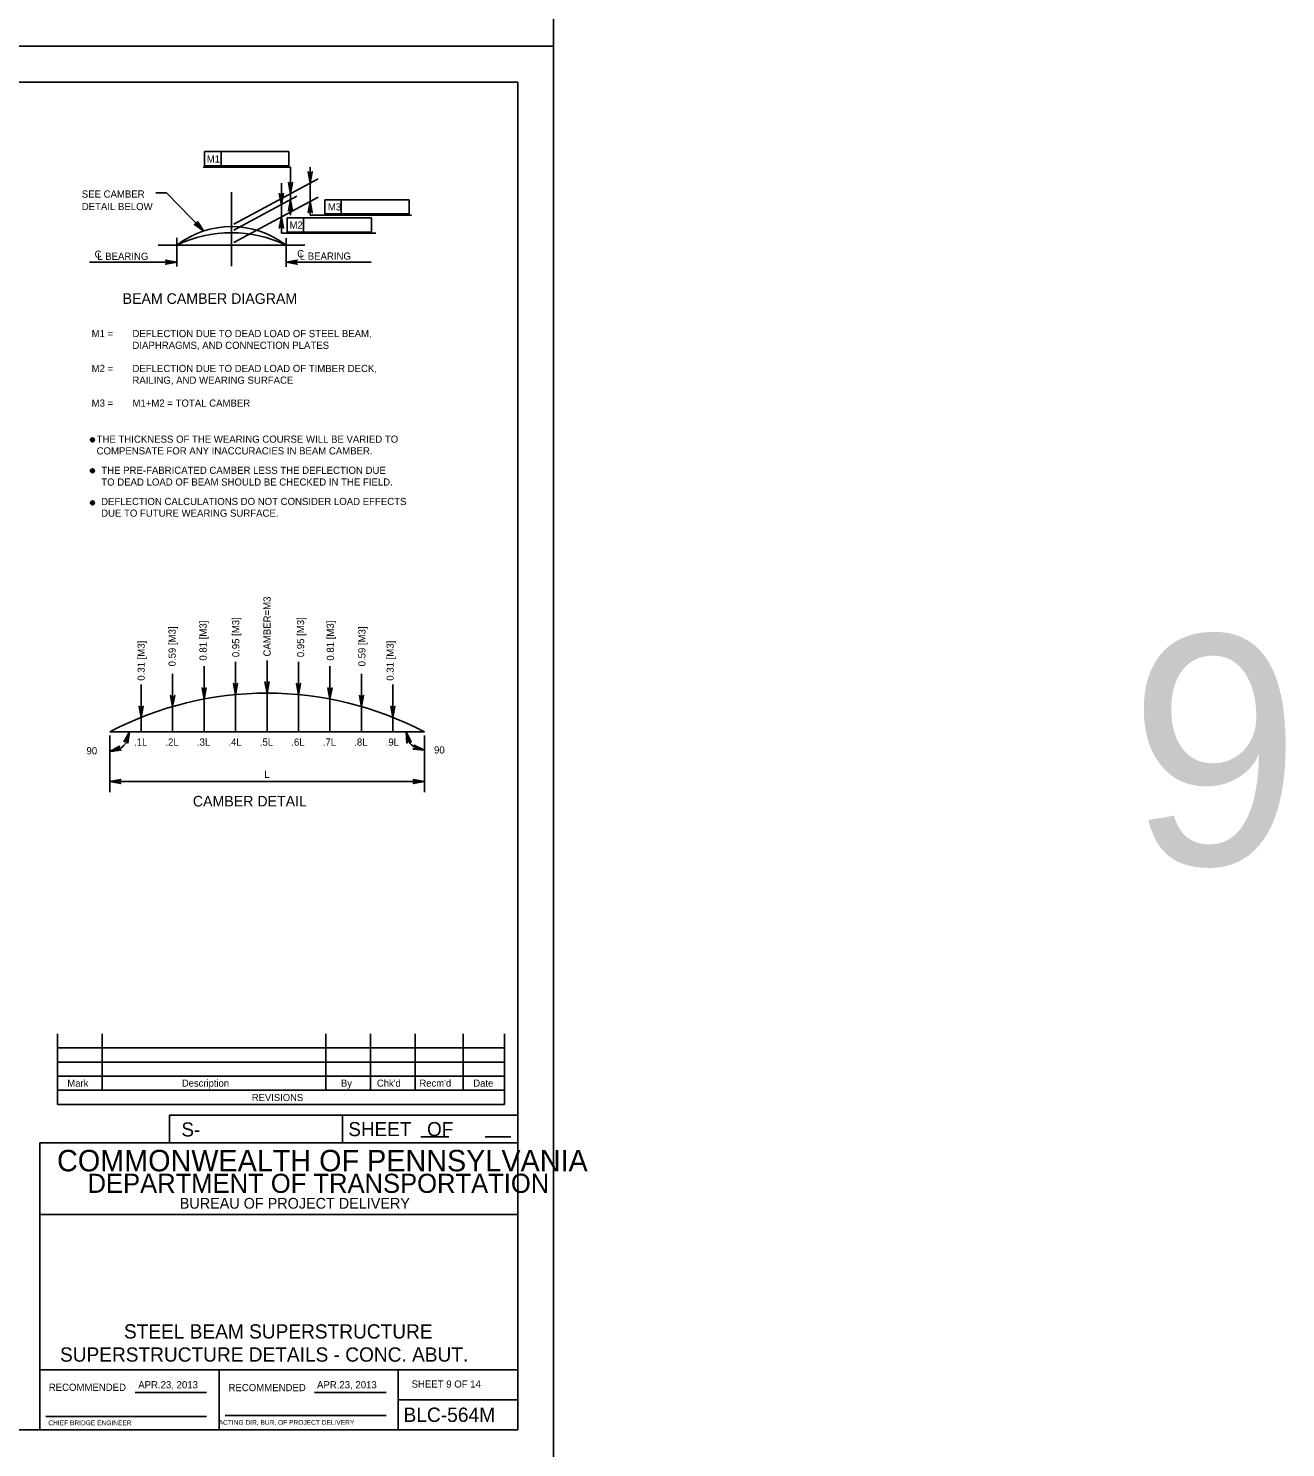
# Model space of a CAD drawing. Extents: x 638175 to 640495, y 294277 to 298435.
# Drawn here: x 639898 to 640424, y 297255 to 297849 of the extents above; entities that cross this region are included whole.
import ezdxf

# ---------------------------------------------------------------- set-up
doc = ezdxf.new("R2010")
doc.units = 0
for name, color, linetype in [('1', 7, 'Continuous'), ('2', 7, 'Continuous'), ('3', 7, 'Continuous'), ('4', 7, 'Continuous'), ('5', 7, 'Continuous'), ('53', 7, 'Continuous'), ('6', 7, 'Continuous'), ('PLT-BNDY', 7, 'Continuous')]:
    doc.layers.add(name, color=color, linetype=linetype)

msp = doc.modelspace()

# ---------------------------------------------------------------- linework, layer by layer
at = {"layer": '2'}
for p, q in [((639316.46, 297826.46), (640102.46, 297826.46)), ((640102.46, 297826.46), (640102.46, 297262.46)), ((639909.92, 297428.15), (639909.92, 297398.62)), ((639928.62, 297428.15), (639928.62, 297404.53)), ((640022.13, 297428.15), (640022.13, 297404.53)), ((640040.83, 297428.15), (640040.83, 297404.53)), ((640059.53, 297428.15), (640059.53, 297404.53)), ((640079.59, 297428.15), (640079.59, 297404.53)), ((640096.94, 297428.15), (640096.94, 297398.62)), ((640096.94, 297422.24), (639909.92, 297422.24)), ((640096.94, 297416.34), (639909.92, 297416.34)), ((640096.94, 297410.43), (639909.92, 297410.43)), ((640096.94, 297404.53), (639909.92, 297404.53)), ((640096.94, 297398.62), (639909.92, 297398.62)), ((640102.46, 297394.11), (639956.78, 297394.11)), ((639956.78, 297394.11), (639956.78, 297382.46)), ((640029.09, 297394.11), (640029.09, 297382.46)), ((640102.46, 297382.46), (639902.46, 297382.46)), ((639902.46, 297382.46), (639902.46, 297262.46)), ((640061.95, 297385), (640073.6, 297385)), ((640088.83, 297385), (640099.56, 297385)), ((640102.46, 297352.46), (639902.46, 297352.46)), ((640102.46, 297287.46), (639902.46, 297287.46)), ((639977.46, 297262.46), (639977.46, 297287.46)), ((640052.46, 297287.46), (640052.46, 297262.46)), ((639942.42, 297277.96), (639972.19, 297277.96)), ((640017.42, 297277.96), (640047.33, 297277.96)), ((640052.46, 297274.96), (640102.46, 297274.96)), ((639904.96, 297267.96), (639972.19, 297267.96)), ((639980.08, 297268.33), (640047.33, 297268.33)), ((640102.46, 297262.46), (639316.46, 297262.46))]:
    msp.add_line(p, q, dxfattribs=at)
at = {"layer": '3'}
for p, q in [((639971.42, 297797.39), (640006.72, 297797.39)), ((639971.42, 297791.48), (639971.42, 297797.39)), ((639978.31, 297791.48), (639978.31, 297797.39)), ((640006.72, 297797.39), (640006.72, 297791.48)), ((640007.35, 297790.9), (639970.86, 297790.9)), ((640006.72, 297791.48), (639971.42, 297791.48)), ((640007.35, 297790.9), (640007.35, 297770.78)), ((640015.62, 297780.3), (640015.62, 297790.9)), ((639983.73, 297767.05), (640018.91, 297786.05)), ((640003.55, 297763.19), (640003.55, 297784.12)), ((639955.5, 297780.06), (639951, 297780.06)), ((639971.05, 297764.14), (639955.5, 297780.06)), ((639982.67, 297749.49), (639982.67, 297780.43)), ((639983.73, 297764.46), (640010.06, 297778.69)), ((639983.73, 297759.29), (640018.91, 297778.3)), ((640015.62, 297780.3), (640015.62, 297770.78)), ((640021.68, 297777.23), (640056.98, 297777.23)), ((640021.68, 297771.32), (640021.68, 297777.23)), ((640028.57, 297771.32), (640028.57, 297777.23)), ((640056.98, 297777.23), (640056.98, 297771.32)), ((640005.95, 297769.61), (640041.25, 297769.61)), ((640005.95, 297763.71), (640005.95, 297769.61)), ((640012.84, 297763.71), (640012.84, 297769.61)), ((640057.99, 297770.78), (640015.62, 297770.78)), ((640056.98, 297771.32), (640021.68, 297771.32)), ((640041.25, 297769.61), (640041.25, 297763.71)), ((639959.79, 297761.27), (639959.79, 297749.35)), ((640043.06, 297763.19), (640003.55, 297763.19)), ((640005.55, 297761.14), (640005.55, 297749.22)), ((640041.25, 297763.71), (640005.95, 297763.71)), ((639959.79, 297751.09), (639923.31, 297751.09)), ((640005.55, 297751.09), (640041.11, 297751.09)), ((639984.39, 297570.12), (639984.39, 297583.84)), ((639997.55, 297570.74), (639997.55, 297584.45)), ((640010.72, 297570.12), (640010.72, 297583.84)), ((639958.05, 297565.13), (639958.05, 297578.84)), ((639971.22, 297568.27), (639971.22, 297581.98)), ((640023.89, 297568.27), (640023.89, 297581.98)), ((640037.05, 297565.13), (640037.05, 297578.84)), ((639944.89, 297560.6), (639944.89, 297574.31)), ((640050.22, 297560.6), (640050.22, 297574.31)), ((639931.72, 297552.97), (639931.72, 297529.28)), ((640063.39, 297552.97), (640063.39, 297529.28)), ((639931.72, 297533.78), (640063.39, 297533.78))]:
    msp.add_line(p, q, dxfattribs=at)
for points in [[(640007.35, 297779.8), (640006.48, 297784.46), (640006.73, 297784.11), (640007.04, 297783.92), (640007.35, 297783.87), (640007.66, 297783.92), (640007.98, 297784.11), (640008.22, 297784.46), (640007.35, 297779.8), (640007.98, 297784.11), (640007.66, 297783.92), (640007.35, 297779.8), (640007.35, 297783.87), (640007.04, 297783.92), (640007.35, 297779.8), (640006.73, 297784.11)], [(640015.62, 297784.27), (640014.75, 297788.93), (640014.99, 297788.57), (640015.31, 297788.39), (640015.62, 297788.33), (640015.93, 297788.39), (640016.24, 297788.57), (640016.49, 297788.93), (640015.62, 297784.27), (640016.24, 297788.57), (640015.93, 297788.39), (640015.62, 297784.27), (640015.62, 297788.33), (640015.31, 297788.39), (640015.62, 297784.27), (640014.99, 297788.57)], [(640003.55, 297775.17), (640002.68, 297779.83), (640002.93, 297779.47), (640003.24, 297779.29), (640003.55, 297779.23), (640003.86, 297779.29), (640004.18, 297779.47), (640004.42, 297779.83), (640003.55, 297775.17), (640004.18, 297779.47), (640003.86, 297779.29), (640003.55, 297775.17), (640003.55, 297779.23), (640003.24, 297779.29), (640003.55, 297775.17), (640002.93, 297779.47)], [(640007.35, 297777.22), (640008.22, 297772.56), (640007.98, 297772.92), (640007.66, 297773.1), (640007.35, 297773.16), (640007.04, 297773.1), (640006.73, 297772.92), (640006.48, 297772.56), (640007.35, 297777.22), (640006.73, 297772.92), (640007.04, 297773.1), (640007.35, 297777.22), (640007.35, 297773.16), (640007.66, 297773.1), (640007.35, 297777.22), (640007.98, 297772.92)], [(640015.62, 297776.52), (640016.49, 297771.86), (640016.24, 297772.22), (640015.93, 297772.4), (640015.62, 297772.46), (640015.31, 297772.4), (640014.99, 297772.22), (640014.75, 297771.86), (640015.62, 297776.52), (640014.99, 297772.22), (640015.31, 297772.4), (640015.62, 297776.52), (640015.62, 297772.46), (640015.93, 297772.4), (640015.62, 297776.52), (640016.24, 297772.22)], [(639971.05, 297764.14), (639967.17, 297766.87), (639967.6, 297766.78), (639967.95, 297766.87), (639968.21, 297767.05), (639968.4, 297767.31), (639968.5, 297767.66), (639968.42, 297768.09), (639971.05, 297764.14), (639968.5, 297767.66), (639968.4, 297767.31), (639971.05, 297764.14), (639968.21, 297767.05), (639967.95, 297766.87), (639971.05, 297764.14), (639967.6, 297766.78)], [(640003.55, 297770), (640004.42, 297765.34), (640004.18, 297765.7), (640003.86, 297765.88), (640003.55, 297765.94), (640003.24, 297765.88), (640002.93, 297765.7), (640002.68, 297765.34), (640003.55, 297770), (640002.93, 297765.7), (640003.24, 297765.88), (640003.55, 297770), (640003.55, 297765.94), (640003.86, 297765.88), (640003.55, 297770), (640004.18, 297765.7)], [(639959.79, 297751.09), (639955.12, 297750.22), (639955.48, 297750.47), (639955.67, 297750.78), (639955.72, 297751.09), (639955.67, 297751.41), (639955.48, 297751.72), (639955.12, 297751.97), (639959.79, 297751.09), (639955.48, 297751.72), (639955.67, 297751.41), (639959.79, 297751.09), (639955.72, 297751.09), (639955.67, 297750.78), (639959.79, 297751.09), (639955.48, 297750.47)], [(640005.55, 297751.09), (640010.21, 297751.97), (640009.85, 297751.72), (640009.67, 297751.41), (640009.61, 297751.09), (640009.67, 297750.78), (640009.85, 297750.47), (640010.21, 297750.22), (640005.55, 297751.09), (640009.85, 297750.47), (640009.67, 297750.78), (640005.55, 297751.09), (640009.61, 297751.09), (640009.67, 297751.41), (640005.55, 297751.09), (640009.85, 297751.72)], [(639971.22, 297568.27), (639970.35, 297572.93), (639970.59, 297572.57), (639970.91, 297572.39), (639971.22, 297572.33), (639971.53, 297572.39), (639971.84, 297572.57), (639972.09, 297572.93), (639971.22, 297568.27), (639971.84, 297572.57), (639971.53, 297572.39), (639971.22, 297568.27), (639971.22, 297572.33), (639970.91, 297572.39), (639971.22, 297568.27), (639970.59, 297572.57)], [(639984.39, 297570.12), (639983.51, 297574.78), (639983.76, 297574.43), (639984.07, 297574.24), (639984.39, 297574.19), (639984.7, 297574.24), (639985.01, 297574.43), (639985.26, 297574.78), (639984.39, 297570.12), (639985.01, 297574.43), (639984.7, 297574.24), (639984.39, 297570.12), (639984.39, 297574.19), (639984.07, 297574.24), (639984.39, 297570.12), (639983.76, 297574.43)], [(639997.55, 297570.74), (639996.68, 297575.4), (639996.93, 297575.04), (639997.24, 297574.85), (639997.55, 297574.8), (639997.86, 297574.85), (639998.18, 297575.04), (639998.42, 297575.4), (639997.55, 297570.74), (639998.18, 297575.04), (639997.86, 297574.85), (639997.55, 297570.74), (639997.55, 297574.8), (639997.24, 297574.85), (639997.55, 297570.74), (639996.93, 297575.04)], [(640010.72, 297570.12), (640009.85, 297574.78), (640010.09, 297574.43), (640010.41, 297574.24), (640010.72, 297574.19), (640011.03, 297574.24), (640011.34, 297574.43), (640011.59, 297574.78), (640010.72, 297570.12), (640011.34, 297574.43), (640011.03, 297574.24), (640010.72, 297570.12), (640010.72, 297574.19), (640010.41, 297574.24), (640010.72, 297570.12), (640010.09, 297574.43)], [(640023.89, 297568.27), (640023.01, 297572.93), (640023.26, 297572.57), (640023.57, 297572.39), (640023.89, 297572.33), (640024.2, 297572.39), (640024.51, 297572.57), (640024.76, 297572.93), (640023.89, 297568.27), (640024.51, 297572.57), (640024.2, 297572.39), (640023.89, 297568.27), (640023.89, 297572.33), (640023.57, 297572.39), (640023.89, 297568.27), (640023.26, 297572.57)], [(639944.89, 297560.6), (639944.01, 297565.26), (639944.26, 297564.9), (639944.57, 297564.72), (639944.89, 297564.66), (639945.2, 297564.72), (639945.51, 297564.9), (639945.76, 297565.26), (639944.89, 297560.6), (639945.51, 297564.9), (639945.2, 297564.72), (639944.89, 297560.6), (639944.89, 297564.66), (639944.57, 297564.72), (639944.89, 297560.6), (639944.26, 297564.9)], [(639958.05, 297565.13), (639957.18, 297569.79), (639957.43, 297569.43), (639957.74, 297569.24), (639958.05, 297569.19), (639958.36, 297569.24), (639958.68, 297569.43), (639958.92, 297569.79), (639958.05, 297565.13), (639958.68, 297569.43), (639958.36, 297569.24), (639958.05, 297565.13), (639958.05, 297569.19), (639957.74, 297569.24), (639958.05, 297565.13), (639957.43, 297569.43)], [(640037.05, 297565.13), (640036.18, 297569.79), (640036.43, 297569.43), (640036.74, 297569.24), (640037.05, 297569.19), (640037.36, 297569.24), (640037.68, 297569.43), (640037.92, 297569.79), (640037.05, 297565.13), (640037.68, 297569.43), (640037.36, 297569.24), (640037.05, 297565.13), (640037.05, 297569.19), (640036.74, 297569.24), (640037.05, 297565.13), (640036.43, 297569.43)], [(640050.22, 297560.6), (640049.35, 297565.26), (640049.59, 297564.9), (640049.91, 297564.72), (640050.22, 297564.66), (640050.53, 297564.72), (640050.84, 297564.9), (640051.09, 297565.26), (640050.22, 297560.6), (640050.84, 297564.9), (640050.53, 297564.72), (640050.22, 297560.6), (640050.22, 297564.66), (640049.91, 297564.72), (640050.22, 297560.6), (640049.59, 297564.9)], [(639940.05, 297554.52), (639939.33, 297549.83), (639939.21, 297550.25), (639938.98, 297550.53), (639938.7, 297550.69), (639938.39, 297550.74), (639938.03, 297550.67), (639937.68, 297550.41), (639940.05, 297554.52), (639938.03, 297550.67), (639938.39, 297550.74), (639940.05, 297554.52), (639938.7, 297550.69), (639938.98, 297550.53), (639940.05, 297554.52), (639939.21, 297550.25)], [(640055.73, 297554.53), (640057.8, 297550.26), (640057.46, 297550.54), (640057.11, 297550.64), (640056.8, 297550.61), (640056.51, 297550.48), (640056.25, 297550.22), (640056.11, 297549.81), (640055.73, 297554.53), (640056.25, 297550.22), (640056.51, 297550.48), (640055.73, 297554.53), (640056.8, 297550.61), (640057.11, 297550.64), (640055.73, 297554.53), (640057.46, 297550.54)], [(639931.73, 297546.24), (639935.89, 297548.51), (639935.62, 297548.16), (639935.55, 297547.81), (639935.59, 297547.5), (639935.74, 297547.22), (639936.01, 297546.98), (639936.43, 297546.85), (639931.73, 297546.24), (639936.01, 297546.98), (639935.74, 297547.22), (639931.73, 297546.24), (639935.59, 297547.5), (639935.55, 297547.81), (639931.73, 297546.24), (639935.62, 297548.16)], [(640063.38, 297546.88), (640058.66, 297547.3), (640059.07, 297547.45), (640059.33, 297547.7), (640059.47, 297547.98), (640059.5, 297548.3), (640059.41, 297548.65), (640059.13, 297548.98), (640063.38, 297546.88), (640059.41, 297548.65), (640059.5, 297548.3), (640063.38, 297546.88), (640059.47, 297547.98), (640059.33, 297547.7), (640063.38, 297546.88), (640059.07, 297547.45)], [(639931.72, 297533.78), (639936.38, 297534.65), (639936.02, 297534.4), (639935.84, 297534.09), (639935.78, 297533.78), (639935.84, 297533.46), (639936.02, 297533.15), (639936.38, 297532.9), (639931.72, 297533.78), (639936.02, 297533.15), (639935.84, 297533.46), (639931.72, 297533.78), (639935.78, 297533.78), (639935.84, 297534.09), (639931.72, 297533.78), (639936.02, 297534.4)], [(640063.39, 297533.78), (640058.72, 297532.9), (640059.08, 297533.15), (640059.27, 297533.46), (640059.32, 297533.78), (640059.27, 297534.09), (640059.08, 297534.4), (640058.72, 297534.65), (640063.39, 297533.78), (640059.08, 297534.4), (640059.27, 297534.09), (640063.39, 297533.78), (640059.32, 297533.78), (640059.27, 297533.46), (640063.39, 297533.78), (640059.08, 297533.15)]]:
    msp.add_lwpolyline(points, dxfattribs=at)
for points in [[(640016.11, 297787.22), (640015.13, 297787.22), (640015.62, 297784.27)], [(640007.84, 297782.76), (640006.86, 297782.76), (640007.35, 297779.8)], [(640004.04, 297778.12), (640003.06, 297778.12), (640003.55, 297775.17)], [(640006.86, 297774.27), (640007.84, 297774.27), (640007.35, 297777.22)], [(640015.13, 297773.57), (640016.11, 297773.57), (640015.62, 297776.52)], [(639968.45, 297767.89), (639967.37, 297766.84), (639971.05, 297764.14)], [(640003.06, 297767.05), (640004.04, 297767.05), (640003.55, 297770)], [(639956.83, 297750.6), (639956.83, 297751.59), (639959.79, 297751.09)], [(640008.5, 297750.6), (640008.5, 297751.59), (640005.55, 297751.09)], [(639971.72, 297571.27), (639970.72, 297571.27), (639971.22, 297568.27)], [(639984.89, 297573.12), (639983.89, 297573.12), (639984.39, 297570.12)], [(639998.05, 297573.74), (639997.05, 297573.74), (639997.55, 297570.74)], [(640011.22, 297573.12), (640010.22, 297573.12), (640010.72, 297570.12)], [(640024.39, 297571.27), (640023.39, 297571.27), (640023.89, 297568.27)], [(639958.55, 297568.13), (639957.55, 297568.13), (639958.05, 297565.13)], [(640037.55, 297568.13), (640036.55, 297568.13), (640037.05, 297565.13)], [(639945.39, 297563.6), (639944.39, 297563.6), (639944.89, 297560.6)], [(640050.72, 297563.6), (640049.72, 297563.6), (640050.22, 297560.6)], [(639934.72, 297534.28), (639934.72, 297533.28), (639931.72, 297533.78)], [(640060.39, 297534.28), (640060.39, 297533.28), (640063.39, 297533.78)]]:
    msp.add_lwpolyline(points, close=True, dxfattribs=at)
for centre, radius in [((639924.52, 297676.74), 0.833), ((639924.52, 297676.74), 0.417), ((639924.52, 297663.81), 0.833), ((639924.52, 297663.81), 0.417), ((639924.52, 297650.38), 0.833), ((639924.52, 297650.38), 0.417)]:
    msp.add_circle(centre, radius, dxfattribs=at)
for centre, radius, start, end in [((639931.72, 297554.54), 8.24, 269.99961, 359.99852), ((640063.38, 297554.54), 7.62, 180.0016, 270.00489)]:
    msp.add_arc(centre, radius, start, end, dxfattribs=at)
at = {"layer": '5'}
for p, q in [((639997.55, 297570.74), (639997.55, 297554.54)), ((639958.05, 297565.13), (639958.05, 297554.54)), ((639971.22, 297568.27), (639971.22, 297554.54)), ((639984.39, 297570.12), (639984.39, 297554.54)), ((640010.72, 297570.12), (640010.72, 297554.54)), ((640023.89, 297568.27), (640023.89, 297554.54)), ((640037.05, 297565.13), (640037.05, 297554.54)), ((639944.89, 297560.6), (639944.89, 297554.54)), ((640050.22, 297560.6), (640050.22, 297554.54)), ((639944.89, 297554.54), (639944.89, 297554.54)), ((639958.05, 297554.54), (639958.05, 297554.54)), ((639971.22, 297554.54), (639971.22, 297554.54)), ((639984.39, 297554.54), (639984.39, 297554.54)), ((639997.55, 297554.54), (639997.55, 297554.54)), ((640010.72, 297554.54), (640010.72, 297554.54)), ((640023.89, 297554.54), (640023.89, 297554.54)), ((640037.05, 297554.54), (640037.05, 297554.54)), ((640050.22, 297554.54), (640050.22, 297554.54))]:
    msp.add_line(p, q, dxfattribs=at)
for centre, radius, start, end in [((639982.67, 297728.32), 37.66, 52.57653, 127.42348), ((639982.67, 297710.14), 53.26, 64.55129, 115.44871), ((639997.55, 297428.87), 141.86, 62.35093, 117.64907)]:
    msp.add_arc(centre, radius, start, end, dxfattribs=at)
at = {"layer": '6'}
for p, q in [((639952.01, 297758.23), (640013.32, 297758.23)), ((639931.72, 297554.54), (640063.39, 297554.54))]:
    msp.add_line(p, q, dxfattribs=at)
at = {"layer": 'PLT-BNDY'}
for points in [[(639276.46, 298435.46), (640117.46, 298435.46), (640117.46, 297841.46), (639276.46, 297841.46)], [(639276.46, 297841.46), (640117.46, 297841.46), (640117.46, 297247.46), (639276.46, 297247.46)]]:
    msp.add_lwpolyline(points, close=True, dxfattribs=at)

# ---------------------------------------------------------------- texts
at = {"layer": '1'}
msp.add_text('SHEET 9 OF 14', height=3, dxfattribs=at).set_placement((640058.05, 297280.07))
at = {"layer": '2'}
for s, height, p in [('Mark', 2.952, (639914.02, 297406.03)), ('Description', 2.9523, (639961.92, 297406.03)), ('By', 2.952, (640028.49, 297406.03)), ("Chk'd", 2.952, (640043.52, 297406.03)), ("Recm'd", 2.953, (640061.33, 297406.03)), ('Date', 2.952, (640083.86, 297406.03)), ('REVISIONS', 2.952, (639991.2, 297400.01)), ('S-', 5.905, (639961.73, 297385.17)), ('COMMONWEALTH OF PENNSYLVANIA', 9, (639909.71, 297370.58)), ('DEPARTMENT OF TRANSPORTATION', 8.0002, (639922.46, 297361.58)), ('BUREAU OF PROJECT DELIVERY', 4.5, (639961.05, 297354.96)), ('SUPERSTRUCTURE DETAILS - CONC. ABUT.', 5.9714, (639910.94, 297290.93)), ('APR.23, 2013', 3, (639943.67, 297279.77)), ('APR.23, 2013', 3, (640018.48, 297279.77)), ('BLC-564M', 6, (640054.64, 297265.71)), ('CHIEF BRIDGE ENGINEER', 2.0002, (639906.05, 297264.33)), ('  ACTING DIR, BUR. OF PROJECT DELIVERY', 2.0002, (639975.78, 297264.51))]:
    msp.add_text(s, height=height, dxfattribs=at).set_placement(p)
for s, height, p in [('SHEET   OF', 5.907, (640031.58, 297385.31)), ('RECOMMENDED', 3, (639906.23, 297278.71)), ('RECOMMENDED', 3, (639981.44, 297278.58))]:
    msp.add_text(s, height=height, rotation=360, dxfattribs=at).set_placement(p)
at = {"layer": '3'}
for s, height, p in [('M1', 3, (639972.33, 297792.78)), ('SEE CAMBER', 3, (639920.04, 297778.13)), ('DETAIL BELOW', 3, (639920.04, 297772.88)), ('M3', 3, (640023.01, 297772.75)), ('M2', 3, (640006.99, 297765.14)), ('C', 3, (639925.41, 297752.97)), ('L BEARING', 3, (639926.5, 297752.07)), ('C', 3, (640010.16, 297753.16)), ('L BEARING', 3, (640011.24, 297752.16)), ('BEAM CAMBER DIAGRAM', 4.4292, (639937.12, 297733.65)), ('M1 =', 3, (639924.17, 297719.72)), ('DEFLECTION DUE TO DEAD LOAD OF STEEL BEAM,', 3, (639941.25, 297719.72)), ('DIAPHRAGMS, AND CONNECTION PLATES', 3, (639941.25, 297714.82)), ('M2 =', 3, (639924.17, 297705.13)), ('DEFLECTION DUE TO DEAD LOAD OF TIMBER DECK,', 3, (639941.25, 297705.13)), ('RAILING, AND WEARING SURFACE', 3, (639941.25, 297700.23)), ('M3 =', 3, (639924.17, 297690.63)), ('M1+M2 = TOTAL CAMBER', 3, (639941.25, 297690.63)), (' THE THICKNESS OF THE WEARING COURSE WILL BE VARIED TO', 3, (639925.15, 297675.54)), (' COMPENSATE FOR ANY INACCURACIES IN BEAM CAMBER.', 3, (639925.15, 297670.64)), ('THE PRE-FABRICATED CAMBER LESS THE DEFLECTION DUE', 3, (639928.22, 297662.5)), ('TO DEAD LOAD OF BEAM SHOULD BE CHECKED IN THE FIELD.', 3, (639928.22, 297657.6)), ('DEFLECTION CALCULATIONS DO NOT CONSIDER LOAD EFFECTS', 3, (639928.14, 297649.46)), ('DUE TO FUTURE WEARING SURFACE.', 3, (639928.14, 297644.57)), ('90', 3, (639922.03, 297545.13)), ('.1L', 3, (639941.95, 297548.75)), ('.2L', 3, (639955.03, 297548.75)), ('.3L', 3, (639968.2, 297548.75)), ('.4L', 3, (639981.37, 297548.75)), ('.5L', 3, (639994.53, 297548.75)), ('.6L', 3, (640007.7, 297548.75)), ('.7L', 3, (640020.87, 297548.75)), ('.8L', 3, (640034.03, 297548.75)), ('.9L', 3, (640047.2, 297548.75)), ('90', 3, (640067.42, 297545.46)), ('L', 3, (639996.39, 297535.24)), ('CAMBER DETAIL', 4.4292, (639966.52, 297523.3))]:
    msp.add_text(s, height=height, dxfattribs=at).set_placement(p)
for s, p in [('CAMBER=M3', (639999.05, 297586.07)), ('0.81 [M3]', (639972.29, 297584.34)), ('0.95 [M3]', (639985.96, 297585.78)), ('0.95 [M3]', (640013.09, 297585.78)), ('0.81 [M3]', (640025.55, 297584.34)), ('0.59 [M3]', (639959.34, 297581.94)), ('0.59 [M3]', (640038.74, 297581.94)), ('0.31 [M3]', (639946.39, 297575.94)), ('0.31 [M3]', (640050.57, 297575.94))]:
    msp.add_text(s, height=3, rotation=90, dxfattribs=at).set_placement(p)
at = {"layer": '4'}
msp.add_text('STEEL BEAM SUPERSTRUCTURE', height=5.9714, dxfattribs=at).set_placement((639937.69, 297300.61))
at = {"layer": '53'}
msp.add_text('9', height=96, dxfattribs=at).set_placement((640358.39, 297498.94))

doc.saveas('drawing.dxf')
